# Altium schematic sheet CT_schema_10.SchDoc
size 391 x 385 mm
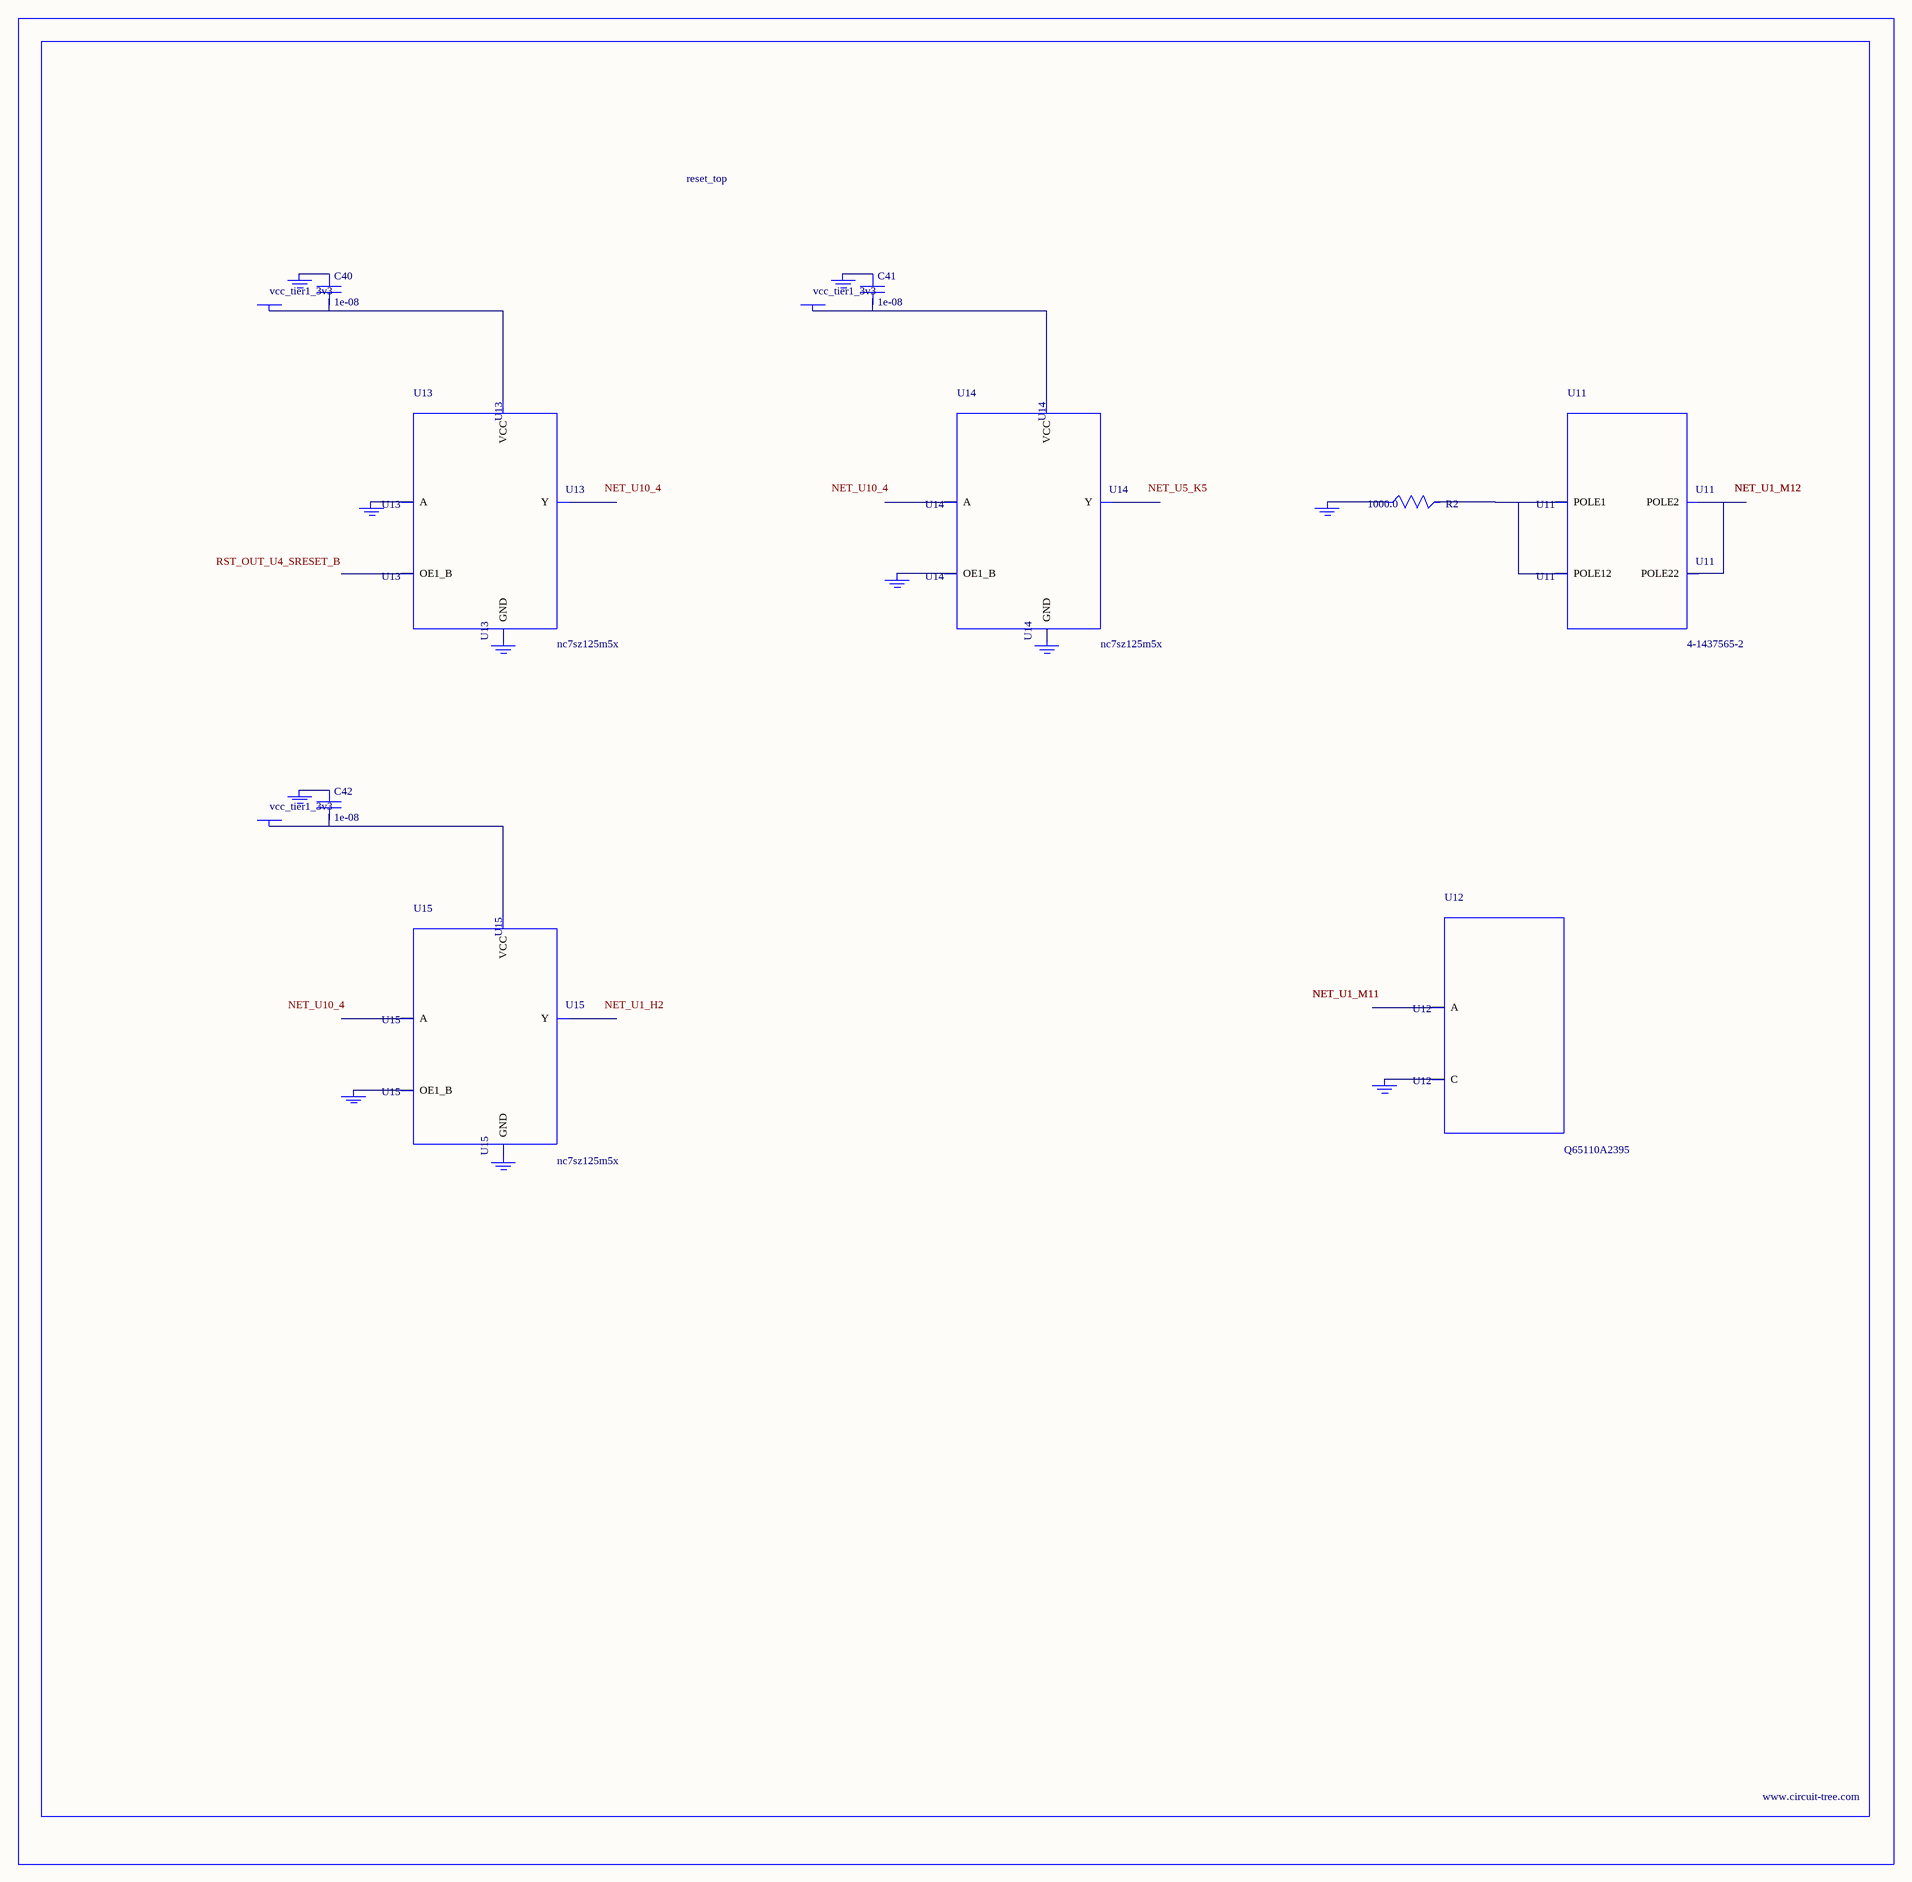
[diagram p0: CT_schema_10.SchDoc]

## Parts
BORDER9  (no value)
C40  1e-08  [C0402]
C41  1e-08  [C0402]
C42  1e-08  [C0402]
GND_INSTANCE_9_0  (no value)
GND_INSTANCE_9_1  (no value)
GND_INSTANCE_9_2  (no value)
GND_INSTANCE_9_3  (no value)
GND_INSTANCE_9_4  (no value)
GND_INSTANCE_9_5  (no value)
GND_INSTANCE_9_6  (no value)
GND_INSTANCE_9_7  (no value)
GND_INSTANCE_9_8  (no value)
GND_INSTANCE_9_9  (no value)
GND_INSTANCE_9_10  (no value)
POWER_INSTANCE_9_0  vcc_tier1_3v3
POWER_INSTANCE_9_1  vcc_tier1_3v3
POWER_INSTANCE_9_2  vcc_tier1_3v3
R2  1000.0  [R0603]
U11  4-1437565-2  [SW_4-1437565-2]
U12  Q65110A2395  [LGM67K-G1J2-24-Z]
U13  nc7sz125m5x  [NC7SZ125M5X]
U14  nc7sz125m5x  [NC7SZ125M5X]
U15  nc7sz125m5x  [NC7SZ125M5X]

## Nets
NetC40_1: C40.1 GND_INSTANCE_9_2.0(GND)
NetC40_2: C40.2 POWER_INSTANCE_9_0.0(PWR) U13.5(VCC)
NetC41_1: C41.1 GND_INSTANCE_9_5.0(GND)
NetC41_2: C41.2 POWER_INSTANCE_9_1.0(PWR) U14.5(VCC)
NetC42_1: C42.1 GND_INSTANCE_9_8.0(GND)
NetC42_2: C42.2 POWER_INSTANCE_9_2.0(PWR) U15.5(VCC)
NetGND_INSTANCE_9_0_0: GND_INSTANCE_9_0.0(GND) R2.1
NetGND_INSTANCE_9_1_0: GND_INSTANCE_9_1.0(GND) U12.C
NetGND_INSTANCE_9_3_0: GND_INSTANCE_9_3.0(GND) U13.2(A)
NetGND_INSTANCE_9_4_0: GND_INSTANCE_9_4.0(GND) U13.3(GND)
NetGND_INSTANCE_9_6_0: GND_INSTANCE_9_6.0(GND) U14.1(OE1_B)
NetGND_INSTANCE_9_7_0: GND_INSTANCE_9_7.0(GND) U14.3(GND)
NetGND_INSTANCE_9_9_0: GND_INSTANCE_9_9.0(GND) U15.1(OE1_B)
NetGND_INSTANCE_9_10_0: GND_INSTANCE_9_10.0(GND) U15.3(GND)
NetR2_2: R2.2 U11.1(POLE1) U11.2(POLE12)
NetU11_3: U11.3(POLE2) U11.4(POLE22)

Not connected (* = marked no-connect by the designer): U12 A; U13 1(OE1_B) 4(Y); U14 2(A) 4(Y); U15 2(A) 4(Y)

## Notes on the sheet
- Labels drawn without touching a wire or pin: NET_U1_H2, NET_U5_K5, NET_U10_4, RST_OUT_U4_SRESET_B

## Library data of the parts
BORDER9 = BORDER_PAGE9
C40-C42 = C0402C103K3RAC
GND_INSTANCE_9_0-GND_INSTANCE_9_10 = GND
POWER_INSTANCE_9_0-POWER_INSTANCE_9_2 = PWR
R2 = RC0603JR-071KL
